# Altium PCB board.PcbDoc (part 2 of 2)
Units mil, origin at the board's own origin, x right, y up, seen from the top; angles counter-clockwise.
Board outline 3925 x 3925 mil, 2 copper layers (Top Layer, Bottom Layer); 233 components, 182 nets, 664 pads, 429 vias.
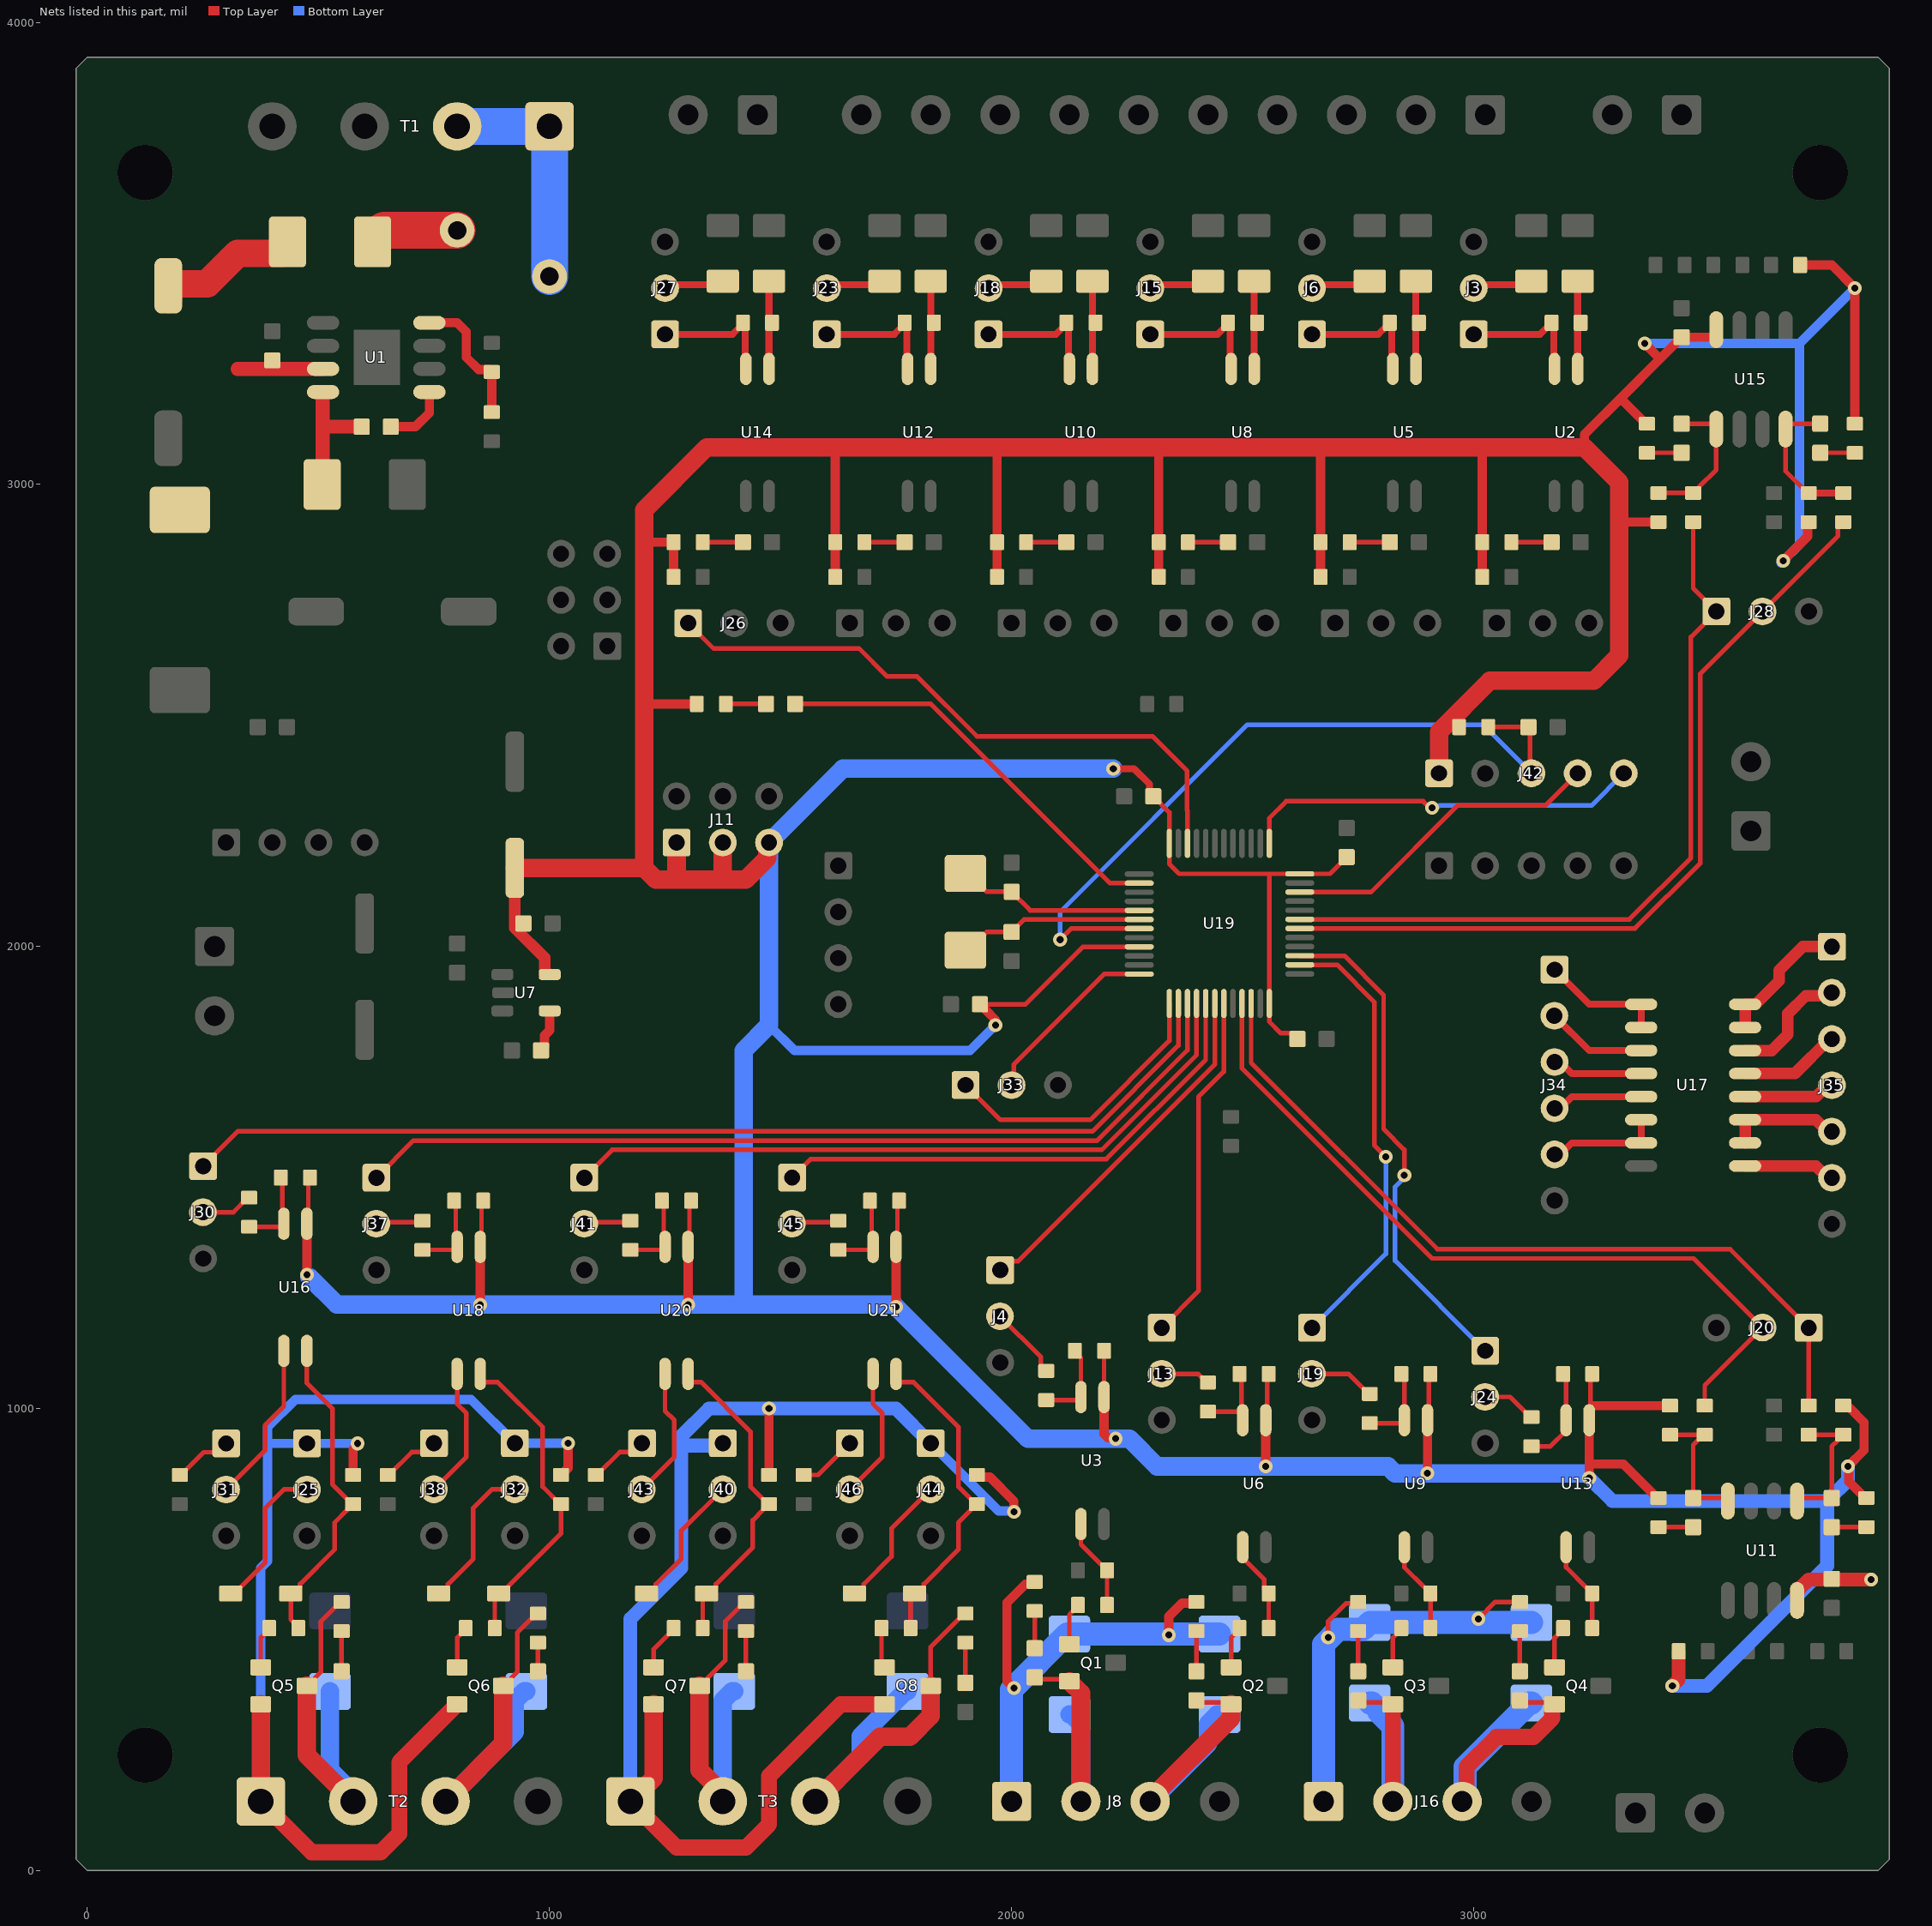
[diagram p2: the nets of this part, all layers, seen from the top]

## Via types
v1: diameter 30, hole 15, Top Layer to Bottom Layer, tented both sides, 423 vias
v2: diameter 30/30 (per signal layer), hole 15, Top Layer to Bottom Layer, tented both sides, 6 vias

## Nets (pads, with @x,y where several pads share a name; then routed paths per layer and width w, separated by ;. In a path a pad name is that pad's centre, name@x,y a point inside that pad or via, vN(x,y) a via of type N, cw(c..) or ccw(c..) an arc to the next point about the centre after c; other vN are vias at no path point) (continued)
INPUT-5: J26.1 U19.46 | length 1369.6
  Top Layer w10: J26.1@1300,2700 1355,2645 1670,2645 1730,2585 1795,2585 1925,2455 2305,2455 2380,2380 2380,2295 2380.61,2294.39 U19.46@2380.61,2223.23
LED-RUN: L19.2 U19.2 | length 905.4
  Top Layer w10: L19.2@1531.49,2525 1825,2525 2212.8,2137.2 U19.2@2276.28,2137.2
NetC1_1: C1.1 L3.1 S2.2 U1.8 | length 300.9
  Top Layer w30: S2.2@508,2985 S2.2@508,3000 509,3001 509,3125 ; U1.8@510,3200 509,3200 509,3125 ; C1.1@593.51,3125.01 509.01,3125.01
NetC1_2: C1.2 U1.1 | length 140.9
  Top Layer w20: C1.2@656.51,3125.01 710.01,3125.01 740,3155 U1.1@740,3200
NetC10_2: C10.2 U7.4 | length 93.4
  Top Layer w20: C10.2@981.51,1775.01 989.01,1782.51 989.01,1807.43 1000.4,1818.82 U7.4@1000.4,1860.63
NetJ3_1: J3.1 R4.2 U2.2 | length 283
  Top Layer w15: J3.1@3000,3325 3143.5,3325 3158.5,3340 3161,3340 3168.5,3347.5 R4.2@3168.5,3350 3173.09,3345.42 3173.09,3251.91 U2.2@3175,3250
NetJ3_2: J3.2 R7.2 | length 131.1
  Top Layer w15: J3.2@3000.28,3424.69 3007.94,3432.34 3117.34,3432.34 R7.2@3125,3440
NetJ4_2: J4.2 R10.1 | length 160.8
  Top Layer w10: J4.2@1975,1200 2063.5,1111.5 2063.5,1091.5 2073.5,1081.5 R10.1@2075,1081.5
NetJ6_1: J6.1 R15.2 U5.2 | length 283
  Top Layer w15: J6.1@2650,3325 2793.5,3325 2808.5,3340 2811,3340 2818.5,3347.5 R15.2@2818.5,3350 2823.09,3345.42 2823.09,3251.91 U5.2@2825,3250
NetJ6_2: J6.2 R18.2 | length 131.1
  Top Layer w15: J6.2@2650.28,3424.69 2657.94,3432.34 2767.34,3432.34 R18.2@2775,3440
NetJ13_2: J13.2 R22.1 | length 108.1
  Top Layer w10: J13.2@2324.72,1075.31 2403.69,1075.31 2422.5,1056.5 R22.1@2425,1056.5
NetJ15_1: J15.1 R25.2 U8.2 | length 283
  Top Layer w15: J15.1@2300,3325 2446,3325 2468.5,3347.5 R25.2@2468.5,3350 2473.09,3345.42 2473.09,3251.91 U8.2@2475,3250
NetJ15_2: J15.2 R27.2 | length 131.1
  Top Layer w15: J15.2@2300.28,3424.69 2307.94,3432.34 2417.34,3432.34 R27.2@2425,3440
NetJ18_1: J18.1 R34.2 U10.2 | length 283
  Top Layer w15: J18.1@1950,3325 2096,3325 2118.5,3347.5 R34.2@2118.5,3350 2123.09,3345.42 2123.09,3251.91 U10.2@2125,3250
NetJ18_2: J18.2 R39.2 | length 131.1
  Top Layer w15: J18.2@1950.28,3424.69 1957.94,3432.34 2067.34,3432.34 R39.2@2075,3440
NetJ19_2: J19.2 R36.1 | length 143.4
  Top Layer w10: J19.2@2649.72,1075.31 2728.69,1075.31 2772.5,1031.5 R36.1@2775,1031.5
NetJ23_1: J23.1 R49.2 U12.2 | length 283
  Top Layer w15: J23.1@1600,3325 1746,3325 1768.5,3347.5 R49.2@1768.5,3350 1773.09,3345.42 1773.09,3251.91 U12.2@1775,3250
NetJ23_2: J23.2 R55.2 | length 131.1
  Top Layer w15: J23.2@1600.28,3424.69 1607.94,3432.34 1717.34,3432.34 R55.2@1725,3440
NetJ24_2: J24.2 R56.1 | length 118.4
  Top Layer w10: J24.2@3024.72,1025.31 3078.69,1025.31 3122.5,981.5 R56.1@3125,981.5
NetJ25_2: J25.2 Z1.2 | length 327
  Top Layer w10: Z1.2@310,600 317.5,600 330,612.5 385,667.5 385,785 425,825 J25.2@475,825
NetJ27_1: J27.1 R61.2 U14.2 | length 283
  Top Layer w15: J27.1@1250,3325 1396,3325 1418.5,3347.5 R61.2@1418.5,3350 1423.09,3345.42 1423.09,3251.91 U14.2@1425,3250
NetJ27_2: J27.2 R64.2 | length 131.1
  Top Layer w15: J27.2@1250.28,3424.69 1257.94,3432.34 1367.34,3432.34 R64.2@1375,3440
NetJ30_2: J30.2 R72.1 | length 118.7
  Top Layer w10: J30.2@250,1400 J30.2@254,1404 ; J30.2@250,1425 316,1425 347.5,1456.5 R72.1@350,1456.5
NetJ31_1: J31.1 R77.2 | length 128.5
  Top Layer w10: R77.2@200,856.5 202.5,856.5 251.69,905.69 281.28,905.69 J31.1@300.28,924.69
NetJ31_2: J31.2 U16.3 | length 351.8
  Top Layer w10: J31.2@300,825 385,910 385,965 425,1005 U16.3@425,1125
NetJ32_2: J32.2 Z2.2 | length 326.9
  Top Layer w10: Z2.2@760,600 767.5,600 780,612.5 780,620 835,675 835,785 875.31,825.31 J32.2@924.72,825.31
NetJ34_1: J34.1 U17.1 U17.2 | length 268.6
  Top Layer w15: J34.1@3175,1950 3250,1875 U17.1@3362.5,1875 U17.2@3362.5,1825
NetJ34_2: J34.2 U17.3 | length 219
  Top Layer w15: J34.2@3174.72,1850.31 3250.03,1775 U17.3@3362.5,1775
NetJ34_3: J34.3 U17.4 | length 197.9
  Top Layer w15: J34.3@3175,1750 3187.18,1750 3212.18,1725 U17.4@3362.5,1725
NetJ34_4: J34.4 U17.5 | length 197.9
  Top Layer w15: J34.4@3175,1650 3187.18,1650 3212.18,1675 U17.5@3362.5,1675
NetJ34_5: J34.5 U17.6 U17.7 | length 247.9
  Top Layer w15: J34.5@3175,1550 3187.18,1550 3212.18,1575 U17.7@3362.5,1575 U17.6@3362.5,1625
NetJ37_2: J37.2 R82.1 | length 102.7
  Top Layer w10: J37.2@625,1400 628.25,1403.25 721.75,1403.25 R82.1@725,1406.5
NetJ38_1: J38.1 R84.2 | length 128.4
  Top Layer w10: R84.2@650,856.5 652.5,856.5 702,906 731,906 J38.1@750,925
NetJ38_2: J38.2 U18.3 | length 287.1
  Top Layer w10: J38.2@749.72,825.31 820,895.6 820,990 800,1010 U18.3@800,1075
NetJ40_2: J40.2 Z3.2 | length 297.9
  Top Layer w10: Z3.2@1210,600 1217.5,600 1230,612.5 1230,620 1285,675 1285,735.6 J40.2@1374.72,825.31
NetJ41_2: J41.2 R90.1 | length 102.7
  Top Layer w10: J41.2@1075,1400 1078.25,1403.25 1171.75,1403.25 R90.1@1175,1406.5
NetJ43_1: J43.1 R92.2 | length 128.4
  Top Layer w10: R92.2@1100,856.5 1102.5,856.5 1152,906 1181,906 J43.1@1200,925
NetJ43_2: J43.2 U20.3 | length 287.1
  Top Layer w10: J43.2@1199.72,825.31 1270,895.6 1270,975 1250,995 U20.3@1250,1075
NetJ44_2: J44.2 Z4.2 | length 297.9
  Top Layer w10: Z4.2@1660,600 1667.5,600 1680,612.5 1680,620 1740,680 1740,740.6 J44.2@1824.72,825.31
NetJ45_2: J45.2 R98.1 | length 102.8
  Top Layer w10: J45.2@1524.72,1400.31 1527.81,1403.41 1621.91,1403.41 R98.1@1625,1406.5
NetJ46_1: J46.1 R100.2 | length 128.4
  Top Layer w10: R100.2@1550,856.5 1581.5,856.5 J46.1@1650,925
NetJ46_2: J46.2 U21.3 | length 287.1
  Top Layer w10: J46.2@1649.72,825.31 1720,895.6 1720,990 1700,1010 U21.3@1700,1075
NetL1_1: L1.1 R2.2 | length 80.5
  Top Layer w10: L1.1@2050,481.49 R2.2@2050,562
NetL2_1: L2.1 R5.2 | length 87
  Top Layer w10: R5.2@3081.5,2875 L2.1@3168.5,2875
NetL4_1: L4.1 R16.2 | length 87
  Top Layer w10: R16.2@2731.5,2875 L4.1@2818.5,2875
NetL5_1: L5.1 R17.2 | length 87
  Top Layer w10: L5.1@2400,431.49 R17.2@2400,518.5
NetL6_1: L6.1 R26.2 | length 87
  Top Layer w10: R26.2@2381.5,2875 L6.1@2468.5,2875
NetL7_1: L7.1 R28.2 | length 87
  Top Layer w10: L7.1@2750,431.49 R28.2@2750,518.5
NetL8_1: L8.1 R35.2 | length 87
  Top Layer w10: R35.2@2031.5,2875 L8.1@2118.5,2875
NetL9_1: L9.1 R33.1 | length 75
  Top Layer w10: L9.1@3775,743.5 R33.1@3850,743.5
NetL9_2: L9.2 R38.1 R40.2 U11.1 | length 296.5
  Top Layer w10: U11.1@3700,800 3706.49,806.49 L9.2@3775,806.49 3775,918.5 3787.5,931 3787.5,933.5 3797.5,943.5 R40.2@3725,943.5
NetL10_1: L10.1 R43.2 | length 87
  Top Layer w10: L10.1@3100,431.49 R43.2@3100,518.5
NetL11_1: L11.1 R50.2 | length 87
  Top Layer w10: R50.2@1681.5,2875 L11.1@1768.5,2875
NetL12_1: L12.1 R52.1 | length 75
  Top Layer w10: R52.1@3400,743.5 L12.1@3475,743.51
NetL12_2: L12.2 R47.2 R51.1 U11.4 | length 299
  Top Layer w10: R51.1@3425,943.5 R47.2@3497.5,943.5 ; R47.2@3500,943.5 R47.2@3497.5,943.5 ; U11.4@3550,800 3543.5,806.5 L12.2@3475,806.5 3475,921 R47.2@3497.5,943.5
NetL13_1: L13.1 R62.2 | length 87
  Top Layer w10: R62.2@1331.5,2875 L13.1@1418.5,2875
NetL14_1: L14.1 R60.1 | length 75
  Top Layer w10: R60.1@3375,3068.5 L14.1@3450,3068.5
NetL14_2: L14.2 R63.1 R65.2 U15.1 | length 316.8
  Top Layer w10: R63.1@3400,2981.5 R65.2@3475,2981.5 3477.5,2981.5 3487.5,2991.5 3487.5,2994 3525,3031.5 U15.1@3525,3120 3525,3122.26 3515.76,3131.49 L14.2@3450,3131.49
NetL15_1: L15.1 R74.2 | length 87
  Top Layer w10: L15.1@550,431.49 R74.2@550,518.5
NetL16_1: L16.1 R78.1 | length 75
  Top Layer w10: L16.1@3750,3068.51 R78.1@3825,3068.5
NetL16_2: L16.2 R73.2 R76.1 U15.4 | length 316.8
  Top Layer w10: R76.1@3725,2981.5 3722.5,2981.5 3675,3029 U15.4@3675,3120 3675,3122.26 3684.24,3131.5 L16.2@3750,3131.5
  Top Layer w15: R76.1@3725,2981.5 R73.2@3800,2981.5
NetL17_1: L17.1 R83.2 | length 62
  Top Layer w10: L17.1@975,431.49 R83.2@975,493.5
NetL18_1: L18.1 R91.2 | length 87
  Top Layer w10: L18.1@1425,431.49 R91.2@1425,518.5
NetL19_1: L19.1 R95.2 | length 87
  Top Layer w10: R95.2@1381.5,2525 L19.1@1468.5,2525
NetL20_1: L20.1 R99.2 | length 87
  Top Layer w10: L20.1@1900,406.49 R99.2@1900,493.5
NetPTC1_2: PTC1.2 S1.1 | length 202.1
  Top Layer w80: S1.1@617,3525 617,3540 632,3540 642,3550 PTC1.2@800,3550
NetQ1_3: Q1.3 R9.1 | length 92.7
  Top Layer w10: Q1.3@2125,490 2125,554 2143.5,572.5 R9.1@2143.5,575
NetQ2_3: Q2.3 R20.1 | length 92.7
  Top Layer w10: Q2.3@2475,440 2475,504 2493.5,522.5 R20.1@2493.5,525
NetQ3_3: Q3.3 R32.1 | length 92.7
  Top Layer w10: Q3.3@2825,440 2825,504 2843.5,522.5 R32.1@2843.5,525
NetQ4_3: Q4.3 R54.1 | length 92.7
  Top Layer w10: Q4.3@3175,440 3175,504 3193.5,522.5 R54.1@3193.5,525
NetQ5_3: Q5.3 R68.1 | length 92.7
  Top Layer w10: Q5.3@375,440 375,504 393.5,522.5 R68.1@393.5,525
NetQ6_3: Q6.3 R80.1 | length 92.7
  Top Layer w10: Q6.3@800,440 800,504 818.5,522.5 R80.1@818.5,525
NetQ7_3: Q7.3 R86.1 | length 103
  Top Layer w10: Q7.3@1225,440 1225,479 1268.5,522.5 R86.1@1268.5,525
NetQ8_3: Q8.3 R96.1 | length 87.7
  Top Layer w10: R96.1@1718.5,525 1718.5,446.5 Q8.3@1725,440
NetR3_2: R3.2 R4.1 U2.1 | length 190
  Top Layer w15: U2.1@3225,3250 R3.2@3225,3440
NetR6_1: R6.1 R12.2 U1.4 | length 295.8
  Top Layer w20: U1.4@740,3350 800,3350 820,3330 820,3275 846.66,3248.34 870.17,3248.34 R12.2@875,3243.5 ; R6.1@875,3156.5 R12.2@875,3241
NetR8_1: R8.1 R10.2 U3.2 | length 183.1
  Top Layer w10: R10.2@2075,1018.5 2143.5,1018.5 U3.2@2150,1025 2150,1109.5 2137,1122.5 R8.1@2137,1125
NetR9_2: R9.2 R11.2 U3.3 | length 199.9
  Top Layer w10: U3.3@2150,750 2150,706.5 2194,662.5 2196.5,662.5 2206.5,652.5 R11.2@2206.5,650 R9.2@2206.5,575
NetR14_2: R14.2 R15.1 U5.1 | length 190
  Top Layer w15: U5.1@2875,3250 R14.2@2875,3440
NetR19_1: R19.1 R22.2 U6.2 | length 176.5
  Top Layer w10: R22.2@2425,993.5 2493.07,993.5 U6.2@2497.13,989.44 ; R19.1@2493.5,1075 2497.13,1071.37 U6.2@2497.13,989.44 ; U6.2@2500,975 2500,986.57 U6.2@2497.13,989.44
NetR20_2: R20.2 R23.2 U6.3 | length 198.4
  Top Layer w10: U6.3@2500,700 2500,677.5 2546.5,631 2546.5,610 R23.2@2556.5,600 R20.2@2556.5,525
NetR24_2: R24.2 R25.1 U8.1 | length 190
  Top Layer w15: U8.1@2525,3250 R24.2@2525,3440
NetR30_2: R30.2 R34.1 U10.1 | length 190
  Top Layer w15: U10.1@2175,3250 R30.2@2175,3440
NetR31_1: R31.1 R36.2 U9.2 | length 180.4
  Top Layer w10: R36.2@2775,968.5 2843.5,968.5 U9.2@2850,975 2850,1068.5 R31.1@2843.5,1075
NetR32_2: R32.2 R37.2 U9.3 | length 199.9
  Top Layer w10: U9.3@2850,700 2850,656.5 2894,612.5 2896.5,612.5 2906.5,602.5 R37.2@2906.5,600 R32.2@2906.5,525
NetR46_2: R46.2 R49.1 U12.1 | length 190
  Top Layer w15: U12.1@1825,3250 R46.2@1825,3440
NetR53_1: R53.1 R56.2 U13.2 | length 214.3
  Top Layer w10: R56.2@3125,918.5 3166,918.5 3200,952.5 U13.2@3200,975 3200,1068.5 R53.1@3193.5,1075
NetR54_2: R54.2 R57.2 U13.3 | length 199.9
  Top Layer w10: U13.3@3200,700 3200,656.5 3244,612.5 3246.5,612.5 3256.5,602.5 R57.2@3256.5,600 R54.2@3256.5,525
NetR59_2: R59.2 R61.1 U14.1 | length 190
  Top Layer w15: U14.1@1475,3250 R59.2@1475,3440
NetR67_1: R67.1 R68.2 U16.4 Z1.1 | length 709
  Top Layer w10: R68.2@456.5,525 456.5,527.5 440,544 Z1.1@440,600 447.5,600 460,612.5 460,620 535,695 535,753.5 562.5,781 562.5,783.5 R67.1@572.5,793.5 ; U16.4@475,1125 475,1055 530,1000 530,836 R67.1@572.5,793.5 ; R67.1@575,793.5 R67.1@572.5,793.5
NetR70_1: R70.1 R72.2 U16.2 | length 180.4
  Top Layer w10: R72.2@350,1393.5 418.5,1393.5 U16.2@425,1400 422.13,1402.87 422.13,1496.37 R70.1@418.5,1500
NetR79_1: R79.1 R80.2 U18.4 Z2.1 | length 705.7
  Top Layer w10: U18.4@850,1075 850,1064.43 856.93,1057.5 887.5,1057.5 985,960 985,831 1022.5,793.5 R79.1@1025,793.5 1025,730 910,615 910,612.5 897.5,600 Z2.1@890,600 881.5,591.5 R80.2@881.5,525
NetR81_1: R81.1 R82.2 U18.2 | length 180.4
  Top Layer w10: R82.2@725,1343.5 793.5,1343.5 U18.2@800,1350 797.13,1352.87 797.13,1446.37 R81.1@793.5,1450
NetR85_1: R85.1 R86.2 U20.4 Z3.1 | length 698.8
  Top Layer w10: U20.4@1300,1075 1300,1064.43 1306.93,1057.5 1327.5,1057.5 1435,950 1435,831 R85.1@1472.5,793.5 ; R86.2@1331.5,525 1331.5,591.5 Z3.1@1340,600 1347.5,600 1360,612.5 1360,620 1440,700 1440,758.5 1462.5,781 1462.5,783.5 R85.1@1472.5,793.5 ; R85.1@1475,793.5 R85.1@1472.5,793.5
NetR89_1: R89.1 R90.2 U20.2 | length 180.4
  Top Layer w10: R90.2@1175,1343.5 1243.5,1343.5 U20.2@1250,1350 1247.13,1352.87 1247.13,1446.37 R89.1@1243.5,1450
NetR93_1: R93.1 R96.2 U21.4 Z4.1 | length 704.7
  Top Layer w10: U21.4@1750,1075 1750,1064.43 1756.93,1057.5 1787.5,1057.5 1885,960 1885,831 R93.1@1922.5,793.5 ; R96.2@1781.5,525 1781.5,591.5 Z4.1@1790,600 1797.5,600 1810,612.5 1810,620 1885,695 1885,753.5 1912.5,781 1912.5,783.5 R93.1@1922.5,793.5 ; R93.1@1925,793.5 R93.1@1922.5,793.5
NetR97_1: R97.1 R98.2 U21.2 | length 177.8
  Top Layer w10: R98.2@1625,1343.5 1693.07,1343.5 1697.13,1347.56 1697.13,1446.37 R97.1@1693.5,1450
NPN-0: D1.1 J8.2 L1.2 Q1.1 | length 550.2
  Top Layer w10: L1.2@2050,418.5 2054.25,414.25 2120.75,414.25 Q1.1@2125,410
  Top Layer w40: Q1.1@2125,410 2150,385 J8.2@2150,150
  Bottom Layer w40: D1.1@2125,338 2130,338 2150,318 J8.2@2150,150
NPN-1: D2.1 J8.3 L5.2 Q2.1 | length 621.1
  Top Layer w10: L5.2@2400,368.5 2404.25,364.25 2470.75,364.25 Q2.1@2475,360
  Top Layer w40: J8.3@2300,150 2300,155 2475,330 Q2.1@2475,360
  Bottom Layer w40: J8.3@2307,150 J8.3@2300,150 2425,275 2425,318 2445,338 D2.1@2450,338
NPN-2: D3.1 J16.2 L7.2 Q3.1 | length 525.2
  Top Layer w10: L7.2@2750,368.5 2754.25,364.25 2820.75,364.25 Q3.1@2825,360
  Top Layer w35: J16.2@2825,150 Q3.1@2825,360
  Bottom Layer w50: D3.1@2775,363 2780,363 2795,348 2795,343 2825,313 J16.2@2825,150
NPN-3: D4.1 J16.3 L10.2 Q4.1 | length 689.2
  Top Layer w10: L10.2@3100,368.5 3104.25,364.25 3165.75,364.25 Q4.1@3170,360
  Top Layer w35: J16.3@2975,150 2984.57,159.57 2984.57,224.57 3049.44,289.44 3129.44,289.44 3170,330 Q4.1@3170,360
  Bottom Layer w50: J16.3@2975,150 2981.7,156.7 2981.7,224.7 3120,363 D4.1@3125,363
NRST: C19.2 J42.3 R94.1 U19.7 | length 1662.1
  Top Layer w10: v1(2105,2015) 2128.78,2038.78 U19.7@2276.28,2038.78 ; R94.1@3031.5,2475 C19.2@3118.49,2474.99 3121.75,2471.74 3121.75,2378.25 J42.3@3125,2375
  Bottom Layer w10: v1(2105,2015) 2105,2075 2510,2480 3020,2480 J42.3@3125,2375
O0: J35.1 U17.15 U17.16 | length 302.6
  Top Layer w25: U17.15@3587.5,1825 U17.16@3587.5,1875 3610,1875 3661.09,1926.09 3661.09,1948.59 3712.19,1999.69 J35.1@3775.28,1999.69
O1: J35.2 U17.14 | length 265.6
  Top Layer w25: U17.14@3587.5,1775 3645,1775 3680,1810 3680,1855 3718.3,1893.3 3768.3,1893.3 J35.2@3775,1900
O2: J35.3 U17.13 | length 218.7
  Top Layer w25: U17.13@3587.5,1725 3695,1725 3769.69,1799.69 J35.3@3775.28,1799.69
O3: J35.4 U17.12 | length 198
  Top Layer w25: U17.12@3587.5,1675 3741.12,1675 3765.81,1699.69 J35.4@3775.28,1699.69
O4: J35.5 U17.10 U17.11 | length 248.3
  Top Layer w25: U17.10@3587.5,1575 U17.11@3587.5,1625 3740.5,1625 3765.81,1599.69 J35.5@3775.28,1599.69
OSC-IN: C14.2 U19.5 Y1.2 | length 409.4
  Top Layer w10: Y1.2@1900,2158 1906.62,2158 1946.13,2118.49 C14.2@2000.01,2118.49 2040.35,2078.15 U19.5@2276.28,2078.15
OSC-OUT: C15.2 U19.6 Y1.1 | length 403.8
  Top Layer w10: Y1.1@1900,1992 1906.62,1992 1946.13,2031.51 C15.2@1999.99,2031.51 2026.95,2058.46 U19.6@2276.28,2058.46
OUT-N-0: J4.1 U19.18 | length 780.8
  Top Layer w10: J4.1@1975.28,1299.69 1994.43,1318.83 2013.83,1318.83 2439.67,1744.67 U19.18@2439.67,1876.77
OUT-N-1: J13.1 U19.19 | length 757.4
  Top Layer w10: J13.1@2325,1175 2404.5,1254.5 2404.5,1674.5 2459.35,1729.35 U19.19@2459.35,1876.77
OUT-N-2: J19.1 U19.26 | length 976.2
  Top Layer w10: U19.26@2623.72,1960.43 2704.57,1960.43 2785,1880 2785,1570 v1(2810,1545)
  Bottom Layer w10: J19.1@2650,1175 2810,1335 v1(2810,1545)
OUT-N-3: J24.1 U19.27 | length 1094.2
  Top Layer w10: U19.27@2623.72,1980.12 2624.07,1979.77 2720.23,1979.77 2805,1895 2805,1605 2850,1560 v1(2850,1505)
  Bottom Layer w10: v1(2850,1505) 2850,1499.59 2830,1479.59 2830,1320 J24.1@3025,1125
OUT-P-0: J30.1 U19.14 | length 2310.1
  Top Layer w10: J30.1@250.28,1524.69 250.28,1525.23 275.28,1550.23 275.28,1550.28 325,1600 2175.09,1600 2360.93,1785.83 U19.14@2360.93,1876.77
OUT-P-1: J37.1 U19.15 | length 1970.8
  Top Layer w10: J37.1@625.28,1499.69 705.6,1580 2185,1580 2380.61,1775.61 U19.15@2380.61,1876.77
OUT-P-2: J41.1 U19.16 | length 1546.5
  Top Layer w10: J41.1@1075.28,1499.69 1135.6,1560 2195,1560 2400.3,1765.3 U19.16@2400.3,1876.77
OUT-P-3: J45.1 U19.17 | length 1122.4
  Top Layer w10: J45.1@1525,1500 1565,1540 2205,1540 2419.98,1754.98 U19.17@2419.98,1876.77
PNP-0: D5.2 Q5.2 R74.1 T2.2 | length 744.4
  Top Layer w10: Q5.2@492.5,412.5 492.5,417.5 505,430 505,539 547.5,581.5 R74.1@550,581.5
  Top Layer w40: Q5.2@475,400 475,250 T2.2@575,150
  Bottom Layer w40: D5.2@525,388 525,217.59 575,167.59 T2.2@575,150
PNP-1: D6.2 Q6.2 R83.1 T2.3 | length 785.1
  Top Layer w10: Q6.2@917.5,412.5 917.5,417.5 930,430 930,515 961.5,546.5 965,546.5 R83.1@975,556.5
  Top Layer w40: T2.3@775,150 900,275 Q6.2@900,400
  Bottom Layer w40: T2.3@775,150 925,300 925,368 945,388 D6.2@950,388
PNP-2: D7.2 Q7.2 R91.1 T3.2 | length 726.6
  Top Layer w10: Q7.2@1342.5,412.5 1342.5,417.5 1380,455 1380,539 1422.5,581.5 R91.1@1425,581.5
  Top Layer w40: Q7.2@1325,400 1325,217.59 1375,167.59 T3.2@1375,150
  Bottom Layer w40: T3.2@1375,150 1375,368 1395,388 D7.2@1400,388
PNP-3: D8.2 Q8.2 R99.1 T3.3 | length 904.4
  Top Layer w10: Q8.2@1825,400 1825,484 1897.5,556.5 R99.1@1900,556.5
  Top Layer w40: T3.3@1575,150 1715,290 1780,290 1825,335 Q8.2@1825,400
  Bottom Layer w40: T3.3@1575,150 1673.12,248.12 1673.12,291.12 1770,388 D8.2@1775,388
RXD-1: J28.1 R65.1 U19.31 | length 1671.8
  Top Layer w10: U19.31@2623.72,2058.86 3337.04,2058.86 3470,2191.82 3470,2669.97 J28.1@3525.31,2725.28 3475,2775.6 R65.1@3475,2918.5
RXD-2: J33.1 U19.13 | length 623.6
  Top Layer w10: J33.1@1900.31,1700.28 1975.6,1625 2170,1625 2341.24,1796.24 U19.13@2341.24,1876.77
RXD-3: J20.1 R40.1 U19.22 | length 1741
  Top Layer w10: U19.22@2518.41,1876.77 2518.41,1748.34 2921.75,1345 3555,1345 J20.1@3725,1175 R40.1@3725,1006.5
SWCLK: J42.5 U19.37 | length 873.9
  Top Layer w10: U19.37@2557.78,2223.23 2557.78,2277.78 2594.34,2314.34 2890.66,2314.34 2905,2300 v1(2910,2300)
  Bottom Layer w10: v1(2910,2300) 2913.83,2303.83 2924.68,2303.83 2925.86,2305 3255,2305 J42.5@3325,2375
SWDIO: J42.4 U19.34 | length 707.8
  Top Layer w10: U19.34@2623.72,2117.91 2777.91,2117.91 2965,2305 3155,2305 J42.4@3225,2375
TXD-1: J28.2 R73.1 U19.30 | length 1792.4
  Top Layer w10: U19.30@2623.72,2039.17 3349.17,2039.17 3490,2180 3490,2590 J28.2@3625,2725 3788.5,2888.5 3788.5,2908.5 3798.5,2918.5 R73.1@3800,2918.5
TXD-2: J33.2 U19.12 | length 399.3
  Top Layer w10: J33.2@2000,1700 2005,1705 2005,1745 2200.35,1940.35 U19.12@2276.28,1940.35
TXD-3: J20.2 R47.1 U19.21 | length 1720.1
  Top Layer w10: U19.21@2498.72,1876.77 2498.72,1736.28 2910,1325 3475.6,1325 J20.2@3625.31,1175.28 3500,1049.97 R47.1@3500,1006.5
VCC: C7.2 C9.2 C11.2 C12.2 C13.1 C16.2 C17.2 C18.1 J11.1 J11.3 J11.5 J42.1 R1.1 R5.1 R8.2 R13.1 R16.1 R19.2 R21.1 R26.1 R29.1 R31.2 R33.2 R35.1 R38.2 R45.1 R48.1 R50.1 R51.2 R52.2 R53.2 R58.1 R60.2 R62.1 R63.2 R70.2 R75.1 R76.2 R78.2 R81.2 R89.2 R94.2 R95.1 R97.2 U3.1 U6.1 U7.5 U9.1 U11.8 U13.1 U15.8 U16.1 U18.1 U19.9 U19.24 U19.36 U19.48 U20.1 U21.1 | length 19594.7
  Top Layer w10: U16.1@475,1400 477.87,1402.87 477.87,1496.37 R70.2@481.5,1500 ; U18.1@850,1350 852.87,1352.87 852.87,1446.37 R81.2@856.5,1450 ; U20.1@1300,1350 1302.87,1352.87 1302.87,1446.37 R89.2@1306.5,1450 ; U21.1@1750,1350 1752.87,1352.87 1752.87,1446.37 R97.2@1756.5,1450 ; C17.2@1943.02,1863.49 1931.51,1863.49 C17.2@1931.51,1875.01 2030.01,1875.01 2154.41,1999.41 U19.9@2276.28,1999.41 ; v1(1965,1830) v1@1965,1841.51 ; U3.1@2200,1025 R8.2@2200,1125 ; C13.1@2306.49,2324.99 2341.24,2290.24 U19.48@2341.24,2223.23 2341.24,2178.76 2362.72,2157.28 2560,2157.28 ; U6.1@2550,975 2552.87,977.87 2552.87,1071.37 R19.2@2556.5,1075 ; C18.1@2618.51,1800.01 2606.01,1812.51 2582.49,1812.51 2557.78,1837.22 U19.24@2557.78,1876.77 2557.78,2155.06 2560,2157.28 ; C16.2@2725.01,2193.49 2688.8,2157.28 U19.36@2623.72,2157.28 2560,2157.28 ; U9.1@2900,975 2902.87,977.87 2902.87,1071.37 R31.2@2906.5,1075 ; U13.1@3252.87,999.02 3252.87,1071.37 R53.2@3256.5,1075
  Top Layer w15: v1(2220,2385) 2265,2385 2298.36,2351.64 2298.36,2333.12 C13.1@2306.49,2324.99
  Top Layer w20: v1(475,1290) U16.1@475,1400 ; v1(850,1225) U18.1@850,1350 ; 1205,2880 1210,2875 R62.1@1268.5,2875 R58.1@1268.5,2800 R58.1@1268.5,2797.5 ; 1220,2525 R95.1@1318.5,2525 ; v1(1300,1225) U20.1@1300,1350 ; R45.1@1618.5,2800 R50.1@1618.5,2875 1618.5,3078.5 1620,3080 ; v1(1750,1220) U21.1@1750,1350 ; C17.2@1943.02,1863.49 v1@1965,1841.51 ; 1965,3080 1968.5,3076.5 R35.1@1968.5,2875 R29.1@1968.5,2800 ; U3.1@2200,1025 2200,945.2 2208.28,936.91 2223.09,936.91 v1(2225,935) ; R21.1@2318.5,2800 R26.1@2318.5,2875 2318.5,3078.5 2320,3080 ; v1(2550,875) U6.1@2550,975 ; 2665,3080 2668.5,3076.5 R16.1@2668.5,2875 R13.1@2668.5,2800 ; v1(2900,860) U9.1@2900,975 ; R1.1@3018.5,2800 R5.1@3018.5,2875 3018.5,3073.5 3025,3080 ; 3240,3080 3240,3108.49 3320.76,3189.24 ; v1(3250,850) 3250,880 ; 3315,2920 3316.5,2918.5 R63.2@3400,2918.5 ; v1(3370,3305) 3403.26,3271.74 ; R60.2@3375,3131.5 3372.5,3131.5 3320.76,3183.24 3320.76,3189.24 ; R52.2@3400,806.5 3397.5,806.5 3324,880 3250,880 ; R51.2@3425,1006.5 3260.35,1006.5 3252.87,999.02 3250,996.15 U13.1@3250,975 3250,880 ; U15.8@3525,3335 3525,3323.11 3520.38,3318.49 C12.2@3450.01,3318.49 3403.26,3271.74 ; v1(3670,2835) 3722.67,2887.67 3722.67,2916.17 R76.2@3725,2918.5 ; R75.1@3706.5,3475 3775,3475 v1(3825,3425) R78.2@3825,3131.5 ; R38.2@3800,1006.5 3805,1001.5 3813.5,1001.5 3845,970 3845,910 v1(3810,875) 3811.91,873.09 3811.91,842.08 3847.5,806.5 R33.2@3850,806.5 ; 3320.76,3189.24 3403.26,3271.74
  Top Layer w25: C7.2@925,2170 925,2040 989.27,1975.73 989.27,1940.06 989.96,1939.37 U7.5@1000.4,1939.37
  Top Layer w30: v1(3430,400) 3443.5,413.5 R48.1@3443.5,475 ; U11.8@3700,585 3700,610 3705,610 3725,630 v1(3860,630)
  Top Layer w40: C7.2@925,2170 1205,2170 ; J11.1@1275,2225 1275,2152.5 1267.5,2145 ; J11.3@1375,2225 1375,2145 ; J11.5@1475,2225 1471.17,2221.17 1471.17,2191.17 1425,2145 1375,2145 ; J42.1@2925,2375 2925,2465 3035,2575 3260,2575 3315,2630 3315,2920 3315,3005 3240,3080 3025,3080 2665,3080 2320,3080 1965,3080 1620,3080 1340,3080 1205,2945 1205,2880 1205,2170 ; 1205,2170 1230,2145 1267.5,2145 ; 1267.5,2145 1375,2145
  Bottom Layer w20: 1475,1830 1530,1775 1910,1775 v1(1965,1830) ; v1(3370,3305) 3705,3305 ; v1@3665,2830 v1(3670,2835) 3705,2870 3705,3305 ; v1(3825,3425) 3705,3305
  Bottom Layer w30: v1@3240,860 v1(3250,850) 3300,800 3765,800 ; v1(3430,400) 3505,400 3737.5,632.5 3765,660 3765,800 ; 3740,630 v1(3860,630) ; v1(3810,875) 3810,845 3770,805 3765,800
  Bottom Layer w40: v1@480,1285 540,1225 v1(850,1225) v1(1300,1225) 1420,1225 ; v1(2220,2385) 1635,2385 J11.5@1475,2225 1475,1830 1420,1775 1420,1225 ; v1@3240,860 v1(2900,860) 2830,860 2815,875 v1(2550,875) 2315,875 2255,935 v1(2225,935) 2035,935 v1(1750,1220) 1745,1225 1420,1225
VCC-N-0: D1.2 D2.2 J8.1 R2.1 R17.1 | length 1124.6
  Top Layer w20: v1(2005,395) 1990,410 1990,580 2030,620 2045,620 R2.1@2050,625 ; v1(2340,510) 2340,550 2369.17,579.16 2397.67,579.16 R17.1@2400,581.5
  Bottom Layer w50: J8.1@2000,150 2000,392 2120,512 D1.2@2125,512 D2.2@2450,512
VCC-N-2: D3.2 D4.2 J16.1 R28.1 R43.1 | length 1031.8
  Top Layer w10: v1(2685,505) 2685,540 2723.36,578.36 2746.86,578.36 R28.1@2750,581.5 ; v1(3010,545) 3046.5,581.5 R43.1@3100,581.5
  Bottom Layer w50: J16.1@2675,150 2675,490 2707,522 2760,522 D3.2@2775,537 D4.2@3125,537
VCC-P: C2.2 C5.2 S1.2 U1.7 | length 523.6
  Top Layer w30: 325,3250 U1.7@510,3250
  Top Layer w60: C2.2@175,3400 C2.2@175,3430 175,3434.25 259.25,3434.25 325,3500 423,3500 433,3510 S1.2@433,3525
VCC-P-0: J25.1 J32.1 Q5.1 Q6.1 R67.2 R79.2 T2.1 | length 2782.3
  Top Layer w20: R67.2@575,856.5 575,912.29 584.69,921.98 v1(584.69,924.69) ; R79.2@1025,856.5 1027.5,856.5 1032.5,861.5 1032.5,864 1040,871.5 v1(1040,925)
  Top Layer w35: T2.1@375,150 485,40 635,40 675,80 675,235 795,355 795,360 Q6.1@800,360
  Top Layer w40: T2.1@375,150 Q5.1@375,360
  Bottom Layer w20: T2.1@375,150 375,655 390,670 390,920 ; v1(584.69,924.69) J25.1@475.28,924.69 394.69,924.69 390,920 ; v1(1040,925) J32.1@925,925 830,1020 450,1020 390,960 390,920
VCC-P-2: J40.1 J44.1 Q7.1 Q8.1 R85.2 R93.2 T3.1 | length 3042.5
  Top Layer w20: R85.2@1475,856.5 v1(1475,1000) ; R93.2@1925,856.5 1929.83,851.66 1953.34,851.66 2004.93,800.07 2004.93,776.56 v1(2005,776.5)
  Top Layer w35: T3.1@1175,150 1275,50 1425,50 1475,100 1475,205 1630,360 Q8.1@1725,360
  Top Layer w40: T3.1@1175,150 1225,200 Q7.1@1225,360
  Bottom Layer w20: J44.1@1825,925 1971.59,778.41 2003.09,778.41 v1(2005,776.5)
  Bottom Layer w30: T3.1@1175,150 1175,545 1285,655 1285,940 1345,1000 v1(1475,1000) 1750,1000 J44.1@1825,925 ; 1290,920 1370,920 J40.1@1375,925
VIN: PTC1.1 T1.1 T1.2 | length 525
  Bottom Layer w80: T1.2@800,3775 T1.1@1000,3775 PTC1.1@1000,3450
VO: J35.6 U17.9 | length 198.3
  Top Layer w25: U17.9@3587.5,1525 3740.5,1525 3765.81,1499.69 J35.6@3775.28,1499.69
pads on no net: J2.3 J4.3 J5.3 J13.3 J14.3 J17.3 J19.3 J22.3 J24.3 J25.3 J26.3 J30.3 J32.3 J37.3 J40.3 J41.3 J44.3 J45.3 U1.2 U1.3 U1.5 U19.1

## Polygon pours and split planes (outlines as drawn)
GND on Top Layer "GND" (solid, remove dead copper, pour order 2): 1125,3075 3225,3075 3350,3200 3349.95,3575.55 3199.85,3725.15 3200.15,3875.38 3225,3900 3550,3900 3575,3875.38 3575.45,3573.52 3612.77,3537.77 3626.03,3525.06 3625,3525.06 3822,3525.53 3875,3475 3875,2250 3775,2150 3625,2150 3500,2025 3125,2025 3075,1975 3075,1450 3175,1350 3700,1350 3875,1175 3875,475 3800,400 3675,400 3600,325 3600,75 3550,25 3325,25 3275,75 3275,225 3375,325 3375,750 3250,875 2325,875 2250,950 2075,950 1800,1225 300,1225 200,1325 200,1600 250,1650 350,1650 475,1775 475,2075 550,2150 650,2150 775,2275 775,2375 950,2550 950,2900
GNDP on Top Layer "GP" (solid, remove dead copper, pour order 0): 1075,3900 1125,3850 1125,3350 925,3150 925,2925 900,2900 900,2575 775,2450 500,2450 425,2375 425,2025 400,2000 400,1800 325,1725 225,1725 200,1700 150,1650 150,1300 300,1150 1725,1150 2025,850 2225,850 2275,800 3225,800 3325,700 3325,350 3225,250 3225,75 3175,25 325,25 275,75 275,350 200,425 75,425 0,500 0,3450 50,3500 200,3500 300,3600 300,3850 350,3900
GNDP on Bottom Layer "GP" (solid, remove dead copper, pour order 1): 1066.32,3908.13 1116.32,3858.13 1116.32,3358.13 916.32,3158.13 916.32,2933.13 891.32,2908.13 891.32,2583.13 766.32,2458.13 491.32,2458.13 416.32,2383.13 416.32,2033.13 400,2016.81 400,1816.81 316.32,1733.13 216.32,1733.13 191.32,1708.13 141.32,1658.13 141.32,1308.13 291.32,1158.13 1716.32,1158.13 2016.32,858.13 2216.32,858.13 2266.32,808.13 3216.32,808.13 3316.32,708.13 3316.32,358.13 3216.32,258.13 3216.32,83.13 3166.32,33.13 316.32,33.13 266.32,83.13 266.32,358.13 191.32,433.13 66.32,433.13 -8.68,508.13 -8.68,3458.13 41.32,3508.13 191.32,3508.13 291.32,3608.13 291.32,3858.13 341.32,3908.13
GND on Bottom Layer "GND" (solid, remove dead copper, pour order 3): 1125,3075 3225,3075 3350,3200 3349.87,3608.11 3225,3725.7 3201.37,3751.06 3201.4,3801.88 3201.45,3873.9 3225,3900 3550,3900 3576.12,3873.9 3574.68,3575.32 3625,3525 3825,3525 3875,3475 3875,2250 3775,2150 3625,2150 3500,2025 3125,2025 3075,1975 3075,1450 3175,1350 3700,1350 3875,1175 3875,475 3800,400 3675,400 3600,325 3600,75 3550,25 3325,25 3275,75 3275,225 3375,325 3375,750 3250,875 2325,875 2250,950 2075,950 1800,1225 300,1225 200,1325 200,1600 250,1650 350,1650 475,1775 475,2075 550,2150 650,2150 775,2275 775,2375 950,2550 950,2900

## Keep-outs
Keep-Out Layer:
  lines w5: -25,25 -25,3900 0,3925 3875,3925 3900,3900 3900,25 3875,0 0,0 -25,25
  lines w60: 1000,3050 1125,3175 1300,3175

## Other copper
Top Layer:
  region net VCC: 940,2120 960,2100 960,2025 1020,1965 1020,1945 980,1945 970,1955 970,1970 900,2040 900,2110 910,2120
  region net 5V: 607.5,2027.5 675,1960 875,1960 885,1950 885,1930 865,1930 860,1925 655,1925 655,1930 595,1990
  region net VCC-P: 175,3415 215,3415 375,3255 465,3255 465,3245 450,3230 325,3230 175,3380
  region net NetC1_1: 480,3200 480,3045 427.5,2992.5 235,2992.5 235,2935 475,2935 475,2959.5 508,2992.5 505,2995.5 505,3195 500,3200
  region net 5V-P: 440,2735 285,2580 230,2580 230,2535 265,2500 340,2500 500,2660 510,2735

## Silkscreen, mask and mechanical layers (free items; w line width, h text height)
Top Overlay:
  text "L5" at 1304.5,3717.5 h48 r180
  text "L4" at 1704.5,3717.5 h48 r180
  text "H4" at 1854.5,3717.5 h48 r180
  text "L3" at 2004.5,3717.5 h48 r180
  text "H3" at 2154.5,3717.5 h48 r180
  text "H5" at 1492,3717 h48 r180
  text "L2" at 2317,3717 h48 r180
  text "H2" at 2467,3717 h48 r180
  text "L1" at 2617,3717 h48 r180
  text "H1" at 2767,3717 h48 r180
  text "L0" at 2892,3717 h48 r180
  text "H0" at 3092,3717 h48 r180
  text "B" at 3292,3717 h48 r180
  text "A" at 3492,3717 h48 r180
  text "GND" at 623.8,3669.55 h48 r180
  text "VIN" at 823.8,3669.55 h48 r180
  text "GND" at 445.52,3669.39 h48 r180
  text "VIN" at 1017,3667 h48 r180
  text "H" at 1167,3292 h48 r180
  text "H" at 1617,3232 h48 r180
  text "H" at 1967,3232 h48 r180
  text "H" at 2317,3232 h48 r180
  text "H" at 2667,3232 h48 r180
  text "H" at 3017,3232 h48 r180
  text "R3" at 3508,2642 h48 r270
  text "T3" at 3608,2642 h48 r270
  text "G" at 3708,2642 h48 r270
  text "ON" at 3008,2583 h48
  text "ON" at 1254.53,2575.13 h48
  text "ON" at 1604.53,2575.13 h48
  text "ON" at 1954.53,2575.13 h48
  text "ON" at 2304.53,2575.13 h48
  text "ON" at 2654.53,2575.13 h48
  text "5V" at 1093,2513 h48
  text "CLK" at 3364,2456 h48 r90
  text "SWIO" at 3271,2450 h48 r90
  text "RUN" at 1465.88,2427.11 h48
  text "GND" at 3517,2358 h48 r90
  text "G" at 2996,2251 h48
  text "V" at 2890,2250 h48
  text "R" at 3097,2249 h48
  text "5V" at 3517,2208 h48 r90
  text "C14" at 1709.47,2152.32 h48
  text "3.3V" at 1308,2108 h48
  text "A8" at 3216,2107 h48 r270
  text "A12" at 3053,2104 h48 r270
  text "A9" at 3295.93,2100.35 h48 r270
  text "B5" at 2895,2099 h48 r270
  text "B4" at 2977,2099 h48 r270
  text "5VP" at 368,2062 h48 r270
  text "C15" at 1702,2049 h48
  text "0" at 3658,1983 h48
  text "A0" at 1713,1955 h48
  text "0" at 3068,1918 h48
  text "GND" at 373,1902 h48 r270
  text "1" at 3683,1883 h48
  text "A1" at 1711,1843 h48
  text "1" at 3066.85,1829.53 h48
  text "2" at 3668,1778 h48
  text "2" at 3071.85,1729.53 h48
  text "3" at 3658,1658 h48
  text "3" at 3066.85,1624.53 h48
  text "R2" at 1857.17,1621.31 h48 r270
  text "T2" at 1982.17,1621.31 h48 r270
  text "G" at 2082.17,1621.31 h48 r270
  text "ON" at 508,1583 h48
  text "4" at 3658,1583 h48
  text "4" at 3071.85,1524.53 h48
  text "ON" at 83,1508 h48
  text "ON" at 908,1483 h48
  text "ON" at 1358,1483 h48
  text "V" at 3653,1483 h48
  text "G" at 3071.85,1424.53 h48
  text "G" at 3658,1373 h48
  text "ON" at 1808,1283 h48
  text "G" at 3542,1258 h48 r90
  text "T1" at 3642,1258 h48 r90
  text "R1" at 3742,1258 h48 r90
  text "ON" at 2158,1233 h48
  text "ON" at 2483,1183 h48
  text "ON" at 2858,1183 h48
  text "H" at 373,1018 h48
  text "H" at 821.84,976.23 h48
  text "H" at 1271.84,971.23 h48
  text "H" at 1721.84,966.23 h48
  text "VP0" at 308,258 h48
  text "P0" at 533,258 h48
  text "GP" at 933,258 h48
  text "VP2" at 1099.43,256.89 h48
  text "P2" at 1324.43,256.89 h48
  text "GP" at 1724.43,256.89 h48
  text "P1" at 728.46,252.21 h48
  text "P3" at 1519.9,251.1 h48
  text "VN0" at 1933,233 h48
  text "N0" at 2108,233 h48
  text "N1" at 2258,233 h48
  text "GP" at 2433,233 h48
  text "VN2" at 2608,233 h48
  text "N2" at 2783,233 h48
  text "N3" at 2933,233 h48
  text "GP" at 3108,233 h48
  text "A" at 3333,233 h48
  text "B" at 3481.37,223.15 h48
